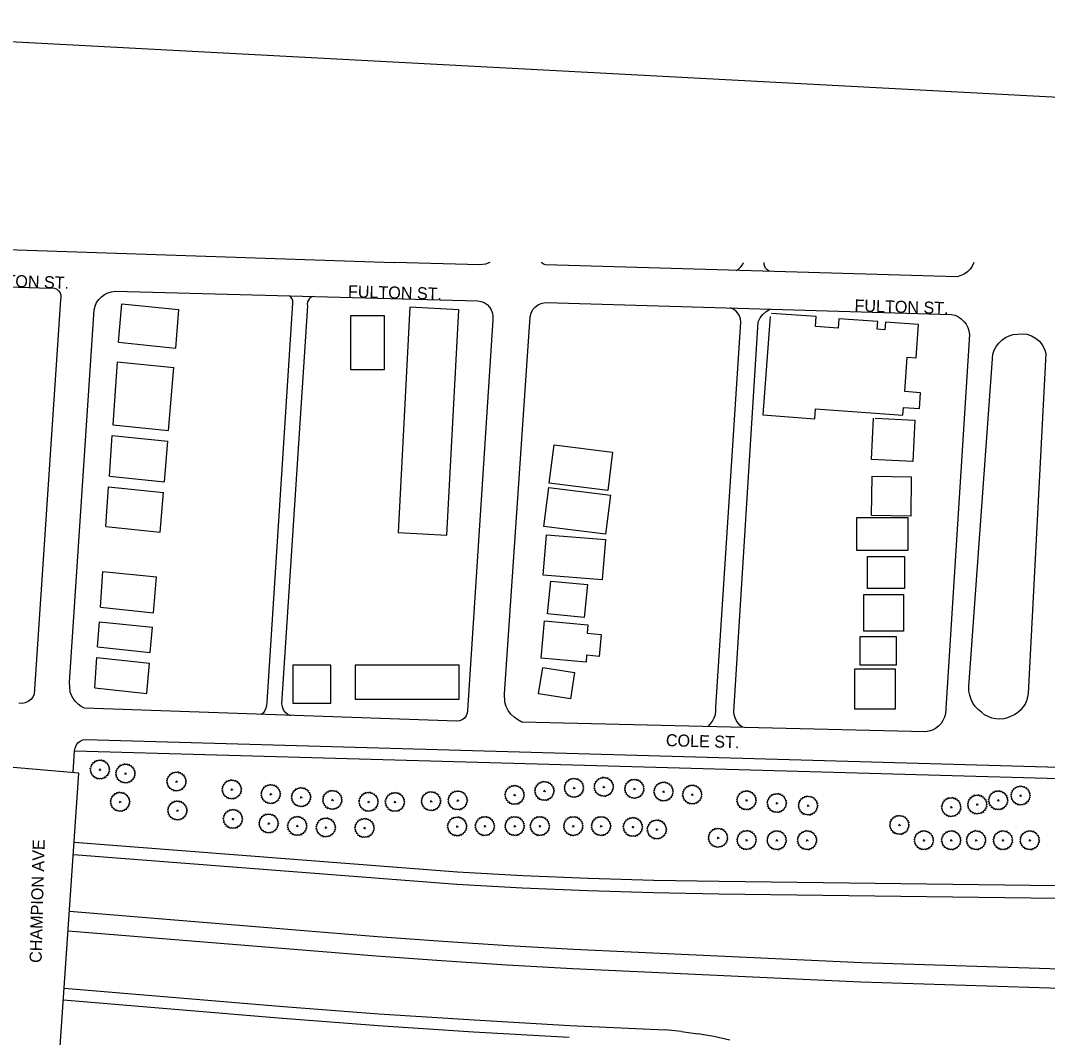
# Model space of a CAD drawing. Extents: x -9648 to 41057, y -12373 to 40276.
# Drawn here: x 12833 to 13685, y -5099 to -4256 of the extents above; entities that cross this region are included whole.
import ezdxf

# ---------------------------------------------------------------- set-up
doc = ezdxf.new("R2010")
doc.units = 0
for name, color, linetype in [('Default', 7, 'Continuous'), ('PM_X_Stop_Line', 7, 'Continuous'), ('SC_Scratch1', 7, 'Continuous'), ('SH_Data', 7, 'Continuous')]:
    doc.layers.add(name, color=color, linetype=linetype)

# ---------------------------------------------------------------- blocks, each defined once
blk = doc.blocks.new('15_PIN')
at = {"layer": 'Default'}
for p, q in [((-2.8, 0), (2.8, 0)), ((0, 2.8), (0, -2.8))]:
    blk.add_line(p, q, dxfattribs=at)
for centre, start, end in [((-25.5, 4.5), 275.99, 64.01), ((-25.9, -1.5), 289.3234, 77.3433), ((-23.8, 10.3), 262.6567, 50.6766), ((-20.8, 15.5), 249.3234, 37.3433), ((-16.7, 19.8), 235.99, 24.01), ((-11.6, 23.2), 222.6567, 10.6766), ((-6, 25.2), 209.3234, 357.3433), ((0, 25.9), 195.99, 344.01), ((6, 25.2), 182.6567, 330.6766), ((11.6, 23.2), 169.3234, 317.3433), ((16.7, 19.8), 155.99, 304.01), ((20.8, 15.5), 142.6567, 290.6766), ((23.8, 10.3), 129.3234, 277.3433), ((25.5, 4.5), 115.99, 264.01), ((25.9, -1.5), 102.6567, 250.6766), ((-24.8, -7.4), 302.6567, 90.6766), ((-22.4, -13), 315.99, 104.01), ((-18.8, -17.8), 329.3234, 117.3433), ((-14.2, -21.6), 342.6567, 130.6766), ((-8.9, -24.3), 355.99, 144.01), ((-3, -25.7), 9.3234, 157.3433), ((3, -25.7), 22.6567, 170.6766), ((8.9, -24.3), 35.99, 184.01), ((14.2, -21.6), 49.3234, 197.3433), ((18.8, -17.8), 62.6567, 210.6767), ((22.4, -13), 75.99, 224.01), ((24.8, -7.4), 89.3234, 237.3433)]:
    blk.add_arc(centre, 3.05, start, end, dxfattribs=at)

msp = doc.modelspace()

# ---------------------------------------------------------------- linework, layer by layer
at = {"layer": 'PM_X_Stop_Line'}
msp.add_arc((9361.23, -8468.95), 3904.03, 82.5, 82.5, dxfattribs=at)
at = {"layer": 'SC_Scratch1'}
msp.add_line((12492.94, -4255.51), (14069.83, -4338.81), dxfattribs=at)
at = {"layer": 'SH_Data'}
for p, q in [((11970.42, -4416.72), (13142.88, -4456.26)), ((13214.08, -4458.26), (13142.88, -4456.26)), ((13218.68, -4457.66), (13214.08, -4458.26)), ((13222.48, -4456.26), (13218.68, -4457.66)), ((13265.88, -4456.86), (13265.08, -4456.26)), ((13266.68, -4457.46), (13265.88, -4456.86)), ((13267.58, -4457.86), (13266.68, -4457.46)), ((13268.48, -4458.26), (13267.58, -4457.86)), ((13610.08, -4468.06), (13268.48, -4458.26)), ((13426.78, -4462.76), (13428.68, -4461.66)), ((13428.68, -4461.66), (13430.38, -4460.06)), ((13430.38, -4460.06), (13431.88, -4458.26)), ((13431.88, -4458.26), (13432.88, -4456.26)), ((13449.98, -4457.86), (13449.88, -4456.26)), ((13450.38, -4459.46), (13449.98, -4457.86)), ((13451.18, -4460.86), (13450.38, -4459.46)), ((13452.28, -4462.06), (13451.18, -4460.86)), ((13453.68, -4463.06), (13452.28, -4462.06)), ((13455.18, -4463.66), (13453.68, -4463.06)), ((13618.58, -4463.96), (13615.98, -4465.86)), ((13620.78, -4461.76), (13618.58, -4463.96)), ((13622.58, -4459.16), (13620.78, -4461.76)), ((13623.88, -4456.26), (13622.58, -4459.16)), ((12511.28, -4466.06), (12857.28, -4477.66)), ((13613.08, -4467.16), (13610.08, -4468.06)), ((13615.98, -4465.86), (13613.08, -4467.16)), ((12857.28, -4477.66), (12859.28, -4477.36)), ((12859.28, -4477.36), (12861.28, -4477.56)), ((12861.28, -4477.56), (12863.18, -4478.36)), ((12863.18, -4478.36), (12864.68, -4479.66)), ((12864.68, -4479.66), (12865.88, -4481.36)), ((12905.48, -4481.36), (12908.58, -4480.46)), ((12908.58, -4480.46), (12911.68, -4480.06)), ((12911.68, -4480.06), (13212.28, -4488.06)), ((12866.08, -4487.26), (12844.48, -4814.46)), ((12865.88, -4481.36), (12866.48, -4483.26)), ((12866.58, -4485.26), (12866.08, -4487.26)), ((12866.48, -4483.26), (12866.58, -4485.26)), ((12894.88, -4492.36), (12896.18, -4489.56)), ((12896.18, -4489.56), (12897.98, -4486.86)), ((12897.98, -4486.86), (12900.18, -4484.66)), ((12900.18, -4484.66), (12902.68, -4482.76)), ((12902.68, -4482.76), (12905.48, -4481.36)), ((13057.38, -4484.96), (13055.98, -4483.86)), ((13058.38, -4486.46), (13057.38, -4484.96)), ((13058.98, -4488.06), (13058.38, -4486.46)), ((13059.08, -4489.86), (13058.98, -4488.06)), ((13071.18, -4488.96), (13070.88, -4490.56)), ((13071.88, -4487.36), (13071.18, -4488.96)), ((13072.88, -4486.06), (13071.88, -4487.36)), ((13074.18, -4485.06), (13072.88, -4486.06)), ((13075.78, -4484.46), (13074.18, -4485.06)), ((13212.28, -4488.06), (13215.08, -4488.56)), ((13215.08, -4488.56), (13217.68, -4489.56)), ((13217.68, -4489.56), (13220.08, -4491.16)), ((13265.78, -4489.96), (13268.88, -4489.46)), ((13268.88, -4489.46), (13605.48, -4499.26)), ((12873.68, -4804.26), (12894.08, -4495.46)), ((12894.08, -4495.46), (12894.88, -4492.36)), ((12914.4, -4522.41), (12917.16, -4490.48)), ((12917.16, -4490.48), (12964.15, -4495.31)), ((12964.15, -4495.31), (12961.52, -4527.25)), ((13037.68, -4821.06), (13059.08, -4489.86)), ((13071.08, -4492.26), (13049.68, -4822.26)), ((13070.88, -4490.56), (13071.08, -4492.26)), ((13156.1, -4493.34), (13146.31, -4680.21)), ((13196.61, -4495.46), (13156.1, -4493.34)), ((13186.83, -4682.33), (13196.61, -4495.46)), ((13220.08, -4491.16), (13222.08, -4493.16)), ((13222.08, -4493.16), (13223.58, -4495.56)), ((13223.58, -4495.56), (13224.58, -4498.26)), ((13256.68, -4498.16), (13258.08, -4495.36)), ((13258.08, -4495.36), (13260.18, -4492.96)), ((13260.18, -4492.96), (13262.78, -4491.06)), ((13262.78, -4491.06), (13265.78, -4489.96)), ((13424.18, -4494.86), (13421.68, -4493.96)), ((13426.38, -4496.36), (13424.18, -4494.86)), ((13428.18, -4498.26), (13426.38, -4496.36)), ((13448.88, -4499.26), (13451.58, -4496.76)), ((13451.58, -4496.76), (13454.78, -4494.86)), ((13106.66, -4500.52), (13106.66, -4545.04)), ((13134.98, -4500.52), (13106.66, -4500.52)), ((13134.98, -4545.04), (13134.98, -4500.52)), ((13224.88, -4503.86), (13203.88, -4827.86)), ((13224.58, -4498.26), (13224.98, -4501.06)), ((13224.98, -4501.06), (13224.88, -4503.86)), ((13234.68, -4814.06), (13255.88, -4501.26)), ((13255.88, -4501.26), (13256.68, -4498.16)), ((13409.88, -4825.26), (13430.68, -4505.66)), ((13424.88, -4829.06), (13444.88, -4505.46)), ((13429.58, -4500.56), (13428.18, -4498.26)), ((13430.38, -4503.06), (13429.58, -4500.56)), ((13430.68, -4505.66), (13430.38, -4503.06)), ((13444.88, -4505.46), (13446.58, -4502.16)), ((13446.58, -4502.16), (13448.88, -4499.26)), ((13454.86, -4501.06), (13448.8, -4582.61)), ((13493.17, -4501.17), (13455.98, -4498.41)), ((13492.56, -4509.42), (13493.17, -4501.17)), ((13511.99, -4502.86), (13511.4, -4510.82)), ((13544.19, -4505.26), (13511.99, -4502.86)), ((13543.71, -4511.65), (13544.19, -4505.26)), ((13550.58, -4505.73), (13550.1, -4512.12)), ((13578.04, -4507.77), (13550.58, -4505.73)), ((13605.48, -4499.26), (13608.38, -4500.06)), ((13608.38, -4500.06), (13611.08, -4501.36)), ((13611.08, -4501.36), (13613.48, -4502.96)), ((13613.48, -4502.96), (13615.68, -4505.06)), ((13615.68, -4505.06), (13617.48, -4507.46)), ((13511.4, -4510.82), (13492.56, -4509.42)), ((13550.1, -4512.12), (13543.71, -4511.65)), ((13576, -4535.24), (13578.04, -4507.77)), ((13617.48, -4507.46), (13618.88, -4510.06)), ((13618.88, -4510.06), (13619.78, -4512.96)), ((13619.78, -4512.96), (13620.28, -4515.86)), ((12914.4, -4522.41), (12961.52, -4527.25)), ((13620.28, -4515.86), (13600.28, -4830.66)), ((13642.48, -4525.86), (13644.58, -4523.06)), ((13644.58, -4523.06), (13647.18, -4520.56)), ((13647.18, -4520.56), (13650.08, -4518.56)), ((13650.08, -4518.56), (13653.18, -4517.06)), ((13653.18, -4517.06), (13656.58, -4516.06)), ((13656.58, -4516.06), (13660.08, -4515.66)), ((13660.08, -4515.66), (13663.98, -4515.36)), ((13663.98, -4515.36), (13667.98, -4515.76)), ((13667.98, -4515.76), (13671.78, -4516.96)), ((13671.78, -4516.96), (13675.18, -4518.96)), ((13675.18, -4518.96), (13678.28, -4521.46)), ((13678.28, -4521.46), (13680.68, -4524.56)), ((13639.68, -4532.26), (13640.78, -4528.96)), ((13640.78, -4528.96), (13642.48, -4525.86)), ((13683.68, -4531.86), (13668.88, -4813.66)), ((13680.68, -4524.56), (13682.58, -4528.06)), ((13682.58, -4528.06), (13683.68, -4531.86)), ((12913.28, -4538.63), (12909.68, -4590.98)), ((12913.28, -4538.63), (12960.18, -4543.46)), ((13566.55, -4563.26), (13568.67, -4534.69)), ((13568.67, -4534.69), (13576, -4535.24)), ((13619.88, -4808.06), (13639.68, -4532.26)), ((12955.87, -4595.73), (12960.18, -4543.46)), ((13106.66, -4545.04), (13134.98, -4545.04)), ((13579.76, -4564.24), (13566.55, -4563.26)), ((13578.78, -4577.45), (13579.76, -4564.24)), ((13448.8, -4582.61), (13492.06, -4585.82)), ((13492.06, -4585.82), (13492.67, -4577.6)), ((13492.67, -4577.6), (13538.49, -4581)), ((13538.49, -4581), (13565.09, -4582.97)), ((13565.09, -4582.97), (13565.57, -4576.47)), ((13565.57, -4576.47), (13578.78, -4577.45)), ((12909.68, -4590.98), (12955.87, -4595.73)), ((13539.02, -4619.64), (13540.73, -4585.35)), ((13541.97, -4585.41), (13575.03, -4587.06)), ((13575.03, -4587.06), (13573.31, -4621.36)), ((12906.74, -4633.57), (12909.07, -4599.82)), ((12909.07, -4599.82), (12955.14, -4604.56)), ((12952.36, -4638.27), (12955.14, -4604.56)), ((13271.69, -4639.3), (13275.67, -4607.53)), ((13275.67, -4607.53), (13324.15, -4613.6)), ((13324.15, -4613.6), (13320.18, -4645.36)), ((13573.31, -4621.36), (13539.02, -4619.64)), ((12906.74, -4633.57), (12952.36, -4638.27)), ((13539.01, -4666.16), (13539.5, -4633.62)), ((13539.5, -4633.62), (13572.03, -4634.11)), ((13572.03, -4634.11), (13571.54, -4666.65)), ((12903.86, -4675.37), (12906.13, -4642.42)), ((12906.13, -4642.42), (12951.63, -4647.09)), ((13267.26, -4675.13), (13271.31, -4642.89)), ((13271.31, -4642.89), (13322.37, -4649.32)), ((13320.18, -4645.36), (13271.69, -4639.3)), ((12948.92, -4680), (12951.63, -4647.09)), ((13322.37, -4649.32), (13318.31, -4681.55)), ((13526.8, -4667.86), (13569.25, -4667.86)), ((13526.8, -4695.12), (13526.8, -4667.86)), ((13571.54, -4666.65), (13539.01, -4666.16)), ((13569.25, -4667.86), (13569.25, -4695.12)), ((12903.86, -4675.37), (12948.92, -4680)), ((13318.31, -4681.55), (13267.26, -4675.13)), ((13146.31, -4680.21), (13186.83, -4682.33)), ((13266.74, -4715.72), (13269.41, -4682.06)), ((13269.41, -4682.06), (13318.2, -4685.93)), ((13318.2, -4685.93), (13315.53, -4719.59)), ((13569.25, -4695.12), (13526.8, -4695.12)), ((13535.71, -4700.1), (13566.38, -4700.1)), ((13535.71, -4726.58), (13535.71, -4700.1)), ((13566.38, -4700.1), (13566.38, -4726.58)), ((12899.26, -4742.26), (12901.31, -4712.53)), ((12901.31, -4712.53), (12945.86, -4717.11)), ((12943.41, -4746.8), (12945.86, -4717.11)), ((13315.53, -4719.59), (13266.74, -4715.72)), ((13270.27, -4747.83), (13272.89, -4720.51)), ((13272.89, -4720.51), (13303.32, -4723.44)), ((13303.32, -4723.44), (13300.7, -4750.76)), ((13566.38, -4726.58), (13535.71, -4726.58)), ((13532.56, -4731.56), (13565.58, -4731.56)), ((13532.56, -4761.96), (13532.56, -4731.56)), ((13565.58, -4731.56), (13565.58, -4761.96)), ((12899.26, -4742.26), (12943.41, -4746.8)), ((13264.94, -4784.42), (13267.64, -4753.62)), ((13267.64, -4753.62), (13303.62, -4756.78)), ((13300.7, -4750.76), (13270.27, -4747.83)), ((12896.99, -4775.19), (12898.43, -4754.3)), ((12898.43, -4754.3), (12942.42, -4758.82)), ((12940.7, -4779.69), (12942.42, -4758.82)), ((13303.62, -4756.78), (13303.01, -4763.79)), ((13565.58, -4761.96), (13532.56, -4761.96)), ((13303.01, -4763.79), (13314.63, -4764.81)), ((13314.63, -4764.81), (13313.04, -4782.99)), ((13529.68, -4766.43), (13559.56, -4766.43)), ((13529.68, -4790.28), (13529.68, -4766.43)), ((13559.56, -4766.43), (13559.56, -4790.28)), ((12896.99, -4775.19), (12940.7, -4779.69)), ((12894.65, -4809.22), (12896.38, -4784.03)), ((12896.38, -4784.03), (12939.97, -4788.52)), ((13302.18, -4787.69), (13264.94, -4784.42)), ((13302.68, -4782.08), (13302.18, -4787.69)), ((13313.04, -4782.99), (13302.68, -4782.08)), ((12937.9, -4813.67), (12939.97, -4788.52)), ((13090.48, -4790.29), (13058.91, -4790.29)), ((13058.91, -4790.29), (13058.91, -4821.85)), ((13090.48, -4821.85), (13090.48, -4790.29)), ((13196.93, -4790.29), (13110.71, -4790.29)), ((13110.71, -4790.29), (13110.71, -4818.62)), ((13196.93, -4818.62), (13196.93, -4790.29)), ((13262.89, -4814.14), (13266.25, -4792.31)), ((13266.25, -4792.31), (13292.61, -4796.37)), ((13525.22, -4793.43), (13558.51, -4793.43)), ((13525.22, -4826.71), (13525.22, -4793.43)), ((13559.56, -4790.28), (13529.68, -4790.28)), ((13558.51, -4793.43), (13558.51, -4826.71)), ((12874.28, -4812.46), (12873.68, -4804.26)), ((13292.61, -4796.37), (13289.25, -4818.2)), ((12875.28, -4815.36), (12874.28, -4812.46)), ((12894.65, -4809.22), (12937.9, -4813.67)), ((13619.88, -4811.86), (13619.88, -4808.06)), ((13620.48, -4815.26), (13619.88, -4811.86)), ((12836.98, -4821.46), (12834.38, -4821.96)), ((12839.38, -4820.46), (12836.98, -4821.46)), ((12841.48, -4818.86), (12839.38, -4820.46)), ((12843.28, -4816.86), (12841.48, -4818.86)), ((12844.48, -4814.46), (12843.28, -4816.86)), ((12876.68, -4818.06), (12875.28, -4815.36)), ((12878.58, -4820.56), (12876.68, -4818.06)), ((12880.78, -4822.76), (12878.58, -4820.56)), ((13037.38, -4823.86), (13037.68, -4821.06)), ((13110.71, -4818.62), (13196.93, -4818.62)), ((13234.88, -4820.86), (13234.68, -4814.06)), ((13235.98, -4824.46), (13234.88, -4820.86)), ((13289.25, -4818.2), (13262.89, -4814.14)), ((13621.58, -4818.66), (13620.48, -4815.26)), ((13623.08, -4821.76), (13621.58, -4818.66)), ((13625.08, -4824.56), (13623.08, -4821.76)), ((13667.68, -4819.76), (13666.38, -4822.56)), ((13668.48, -4816.76), (13667.68, -4819.76)), ((13668.88, -4813.66), (13668.48, -4816.76)), ((12834.38, -4821.96), (12831.68, -4821.86)), ((12883.28, -4824.46), (12880.78, -4822.76)), ((12886.08, -4825.86), (12883.28, -4824.46)), ((13194.88, -4836.86), (12886.08, -4825.86)), ((13033.08, -4831.06), (13035.08, -4829.06)), ((13035.08, -4829.06), (13036.58, -4826.56)), ((13036.58, -4826.56), (13037.38, -4823.86)), ((13049.68, -4822.26), (13049.98, -4824.46)), ((13049.98, -4824.46), (13050.68, -4826.46)), ((13050.68, -4826.46), (13051.78, -4828.36)), ((13051.78, -4828.36), (13053.38, -4829.96)), ((13053.38, -4829.96), (13055.18, -4831.16)), ((13058.91, -4821.85), (13090.48, -4821.85)), ((13203.58, -4830.16), (13202.68, -4832.36)), ((13203.88, -4827.86), (13203.58, -4830.16)), ((13237.58, -4827.86), (13235.98, -4824.46)), ((13239.78, -4830.96), (13237.58, -4827.86)), ((13409.48, -4831.16), (13409.88, -4828.26)), ((13409.88, -4828.26), (13409.88, -4825.26)), ((13425.18, -4831.56), (13424.88, -4829.06)), ((13558.51, -4826.71), (13525.22, -4826.71)), ((13627.58, -4827.16), (13625.08, -4824.56)), ((13630.28, -4829.26), (13627.58, -4827.16)), ((13632.88, -4831.36), (13630.28, -4829.26)), ((13660.38, -4829.66), (13657.68, -4831.36)), ((13662.68, -4827.56), (13660.38, -4829.66)), ((13664.68, -4825.26), (13662.68, -4827.56)), ((13666.38, -4822.56), (13664.68, -4825.26)), ((13055.18, -4831.16), (13057.18, -4831.96)), ((13197.18, -4836.56), (13194.88, -4836.86)), ((13199.38, -4835.66), (13197.18, -4836.56)), ((13201.28, -4834.26), (13199.38, -4835.66)), ((13202.68, -4832.36), (13201.28, -4834.26)), ((13242.48, -4833.56), (13239.78, -4830.96)), ((13245.48, -4835.76), (13242.48, -4833.56)), ((13248.88, -4837.46), (13245.48, -4835.76)), ((13583.68, -4845.46), (13248.88, -4837.46)), ((13405.48, -4839.06), (13407.18, -4836.66)), ((13407.18, -4836.66), (13408.58, -4833.96)), ((13408.58, -4833.96), (13409.48, -4831.16)), ((13425.88, -4834.06), (13425.18, -4831.56)), ((13426.88, -4836.36), (13425.88, -4834.06)), ((13428.28, -4838.46), (13426.88, -4836.36)), ((13430.08, -4840.26), (13428.28, -4838.46)), ((13596.68, -4838.76), (13594.58, -4840.96)), ((13598.28, -4836.26), (13596.68, -4838.76)), ((13599.58, -4833.56), (13598.28, -4836.26)), ((13600.28, -4830.66), (13599.58, -4833.56)), ((13635.68, -4832.96), (13632.88, -4831.36)), ((13638.78, -4834.16), (13635.68, -4832.96)), ((13642.08, -4834.86), (13638.78, -4834.16)), ((13645.38, -4835.06), (13642.08, -4834.86)), ((13648.68, -4834.76), (13645.38, -4835.06)), ((13651.88, -4833.96), (13648.68, -4834.76)), ((13654.88, -4832.66), (13651.88, -4833.96)), ((13657.68, -4831.36), (13654.88, -4832.66)), ((13403.38, -4841.16), (13405.48, -4839.06)), ((13432.08, -4841.86), (13430.08, -4840.26)), ((13586.68, -4845.06), (13583.68, -4845.46)), ((13589.48, -4844.16), (13586.68, -4845.06)), ((13592.18, -4842.76), (13589.48, -4844.16)), ((13594.58, -4840.96), (13592.18, -4842.76)), ((12879.18, -4856.86), (12880.68, -4854.86)), ((12880.68, -4854.86), (12882.48, -4853.36)), ((12882.48, -4853.36), (12884.68, -4852.36)), ((12884.68, -4852.36), (12887.08, -4851.86)), ((12887.08, -4851.86), (14006.88, -4883.86)), ((12876.68, -4879.46), (12877.88, -4861.46)), ((12877.88, -4861.46), (12878.28, -4859.06)), ((12877.89, -4861.38), (14020.89, -4893.32)), ((12878.28, -4859.06), (12879.18, -4856.86)), ((12881.48, -4879.86), (12826.88, -4875.06)), ((12864.68, -5124.66), (12881.48, -4879.86)), ((13195.65, -4962.09), (12877.65, -4937.29)), ((12876.88, -4947.26), (13194.88, -4972.06)), ((13249.81, -4964.98), (13195.41, -4962.08)), ((13304.1, -4967.27), (13249.7, -4964.97)), ((13194.88, -4972.06), (13249.28, -4974.96)), ((13249.28, -4974.96), (13303.68, -4977.26)), ((13358.37, -4968.87), (13303.97, -4967.27)), ((13412.66, -4969.86), (13358.26, -4968.86)), ((13692.8, -4973.46), (13412.6, -4969.86)), ((13303.68, -4977.26), (13358.08, -4978.86)), ((13358.08, -4978.86), (13412.48, -4979.86)), ((13412.48, -4979.86), (13692.68, -4983.46)), ((12873.68, -4994.26), (13075.08, -5011.06)), ((12872.48, -5010.76), (13073.68, -5027.06)), ((13075.08, -5011.06), (13129.18, -5015.36)), ((13129.18, -5015.36), (13183.28, -5019.26)), ((13183.28, -5019.26), (13237.48, -5022.76)), ((13237.48, -5022.76), (13291.68, -5025.86)), ((13291.68, -5025.86), (13531.08, -5037.06)), ((13073.68, -5027.06), (13127.98, -5031.36)), ((13127.98, -5031.36), (13182.18, -5035.26)), ((13182.18, -5035.26), (13236.58, -5038.76)), ((13236.58, -5038.76), (13290.88, -5041.86)), ((13290.88, -5041.86), (13530.28, -5053.06)), ((13531.08, -5037.06), (14007.28, -5051.86)), ((12869.28, -5058.16), (13051.28, -5073.46)), ((13530.28, -5053.06), (14006.18, -5067.86)), ((13050.44, -5083.43), (12868.44, -5068.13)), ((13051.28, -5073.46), (13130.38, -5079.46)), ((13129.62, -5089.43), (13050.52, -5083.43)), ((13130.38, -5079.46), (13209.48, -5084.66)), ((13209.48, -5084.66), (13288.68, -5089.16)), ((13208.82, -5094.64), (13129.72, -5089.44)), ((13288.68, -5089.16), (13367.88, -5092.86)), ((13381.38, -5094.16), (13367.88, -5092.86)), ((13381.38, -5094.16), (13394.88, -5096.06)), ((13288.11, -5099.15), (13208.91, -5094.65)), ((13408.18, -5098.46), (13394.88, -5096.06)), ((13421.48, -5101.46), (13408.18, -5098.46))]:
    msp.add_line(p, q, dxfattribs=at)

# ---------------------------------------------------------------- block references
at = {"layer": 'SH_Data', "xscale": 0.32808397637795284, "yscale": 0.32808397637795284, "rotation": 64.61472397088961}
for p in [(12898.92, -4876.87), (12920.1, -4880.18), (12920.1, -4880.18), (12962.44, -4886.8), (13292.21, -4892.08), (13316.91, -4891.27), (13008.31, -4893.4), (13040.64, -4897.26), (13065.79, -4899.82), (13242.91, -4897.96), (13267.67, -4894.65), (13342.27, -4892.87), (13366.5, -4895.15), (13390.26, -4897.65), (13390.26, -4897.65), (13662.67, -4898.46), (12915.64, -4903.66), (13091.73, -4902.09), (13121.79, -4903.67), (13143.64, -4903.8), (13173.6, -4903.15), (13195.75, -4902.43), (13435.31, -4902.38), (13460.47, -4904.64), (13486.36, -4906.8), (13605.17, -4908.05), (13626.76, -4905.86), (13644.11, -4902.38), (12963.2, -4910.86), (13009.25, -4917.88), (13038.93, -4921.58), (13062.6, -4923.69), (13086.34, -4924.9), (13118.45, -4925.36), (13195.28, -4924.04), (13218.27, -4923.79), (13218.27, -4923.79), (13243.01, -4923.78), (13263.91, -4923.78), (13291.64, -4923.78), (13314.66, -4923.78), (13341.05, -4924.53), (13562.12, -4922.84), (13360.92, -4926.57), (13411.68, -4933.49), (13435.4, -4935.36), (13460.36, -4935.53), (13485.56, -4935.53), (13582.47, -4935.53), (13605.09, -4935.53), (13625.76, -4935.53), (13648.05, -4935.53), (13670.26, -4935.53)]:
    msp.add_blockref('15_PIN', p, dxfattribs=at)

# ---------------------------------------------------------------- texts
at = {"layer": 'SC_Scratch1'}
for s, rotation, p in [('FULTON ST.', 358.07981, (12795.19, -4475.51)), ('FULTON ST.', 358.47552, (13104.61, -4485.12)), ('FULTON ST.', 358.33234, (13524.81, -4496.84)), ('COLE ST.', 358.36313, (13368.32, -4857.47)), ('CHAMPION AVE', 88.50218, (12850.49, -5037.4))]:
    msp.add_text(s, height=10, rotation=rotation, dxfattribs=at).set_placement(p)

doc.saveas('drawing.dxf')
